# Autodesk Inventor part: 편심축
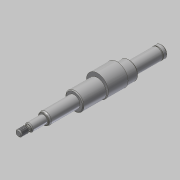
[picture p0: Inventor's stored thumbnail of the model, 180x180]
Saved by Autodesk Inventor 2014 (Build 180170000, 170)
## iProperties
Created: 2015-09
Part Number: 편심축
Material: 강철, 연강
Document SubType Name: Modeling
Designer: mduedu
Density: 1 g/cm^3
Appearance: Steel
Author: mduedu
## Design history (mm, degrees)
sketch "스케치1"
  geometry: L1 (-91, 0)-(91, 0); L2 (-91, 0)-(-91, 7.5); L3 (-91, 7.5)-(-49.85, 7.5); L4 (-49.85, 7.5)-(-49.85, 11.5); L5 (-49.85, 11.5)-(20.15, 11.5); L6 (20.15, 11.5)-(20.15, 7.5); L7 (20.15, 7.5)-(59.15, 7.5); L8 (59.15, 7.5)-(59.15, 5); L9 (59.15, 5)-(78.15, 5); L10 (78.15, 5)-(78.15, 3); L11 (78.15, 3)-(80.15, 3); L12 (81.882, 4)-(91, 4); L13 (91, 4)-(91, 0); L14 (80.15, 3)-(81.882, 4); 2 further points
  constraints: 28 end point, 9 parallel, 2 perpendicular, 1 coincident, 1 collinear, 1 horizontal, 1 midpoint
  dimensions: "d0" = 41.15 distance of L2.end L3.end; "d2" = 70 distance of L4.end L5.end; "d3" = 39 distance of L6.end L7.end; "d4" = 182 distance of L1.start L1.end; "d5" = 19 distance of L8.end L9.end; "d7" = 8 diameter of L12 L1; "d8" = 6 diameter of L11 L1; "d9" = 10 diameter of L9 L1; "d10" = 15 diameter of L7 L1; "d11" = 23 diameter of L5 L1; "d12" = 15 diameter of L3 L1; "d40" = 30 deg angle of L14 L12; "d41" = 2 distance of L10.end L11.end; "d42" = 3.73205 horizontal distance of L12.start L10.end (derived)
revolve "회전1" sketch "스케치1" stored, may be unused: angle "d13" = 90 deg
fillet "모깎기1" dims "d43" = 0.6
sketch "스케치2"
  geometry: L1 (-91, 7.5)-(-49.85, 7.5) reference; L2 (-91, -7.5)-(-91, 7.5) reference; L3 (91, -4)-(91, 4) reference; L4 (-91, 0)-(91, 0); L5 (-86, 7.5)-(-84.85, 7.5); L6 (-84.85, 7.5)-(-84.85, 7.15); L7 (-84.85, 7.15)-(-86, 7.15); L8 (-86, 7.15)-(-86, 7.5); 1 further point
  constraints: 10 end point, 2 midpoint, 2 parallel, 1 horizontal, 1 perpendicular, 1 point on line
  dimensions: "d14" = 5 distance between parallel lines of L8 L2; "d15" = 14.3 diameter of L7 L4; "d16" = 1.15 distance of L6.end L7.end
revolve "회전2" sketch "스케치2" stored, may be unused: angle "d17" = 90 deg
node "작업 평면1"
sketch "스케치3"
  geometry: C1 r 11.5 at (0, 0) reference; C2 r 14 at (0, 2.5); 1 further point
  constraints: 1 centre point, 1 tangent, 1 vertical alignment
  dimensions: "d19" = 28 diameter of C2
extrude "돌출1" join sketch "스케치3" distance "d21" = 25; taper "d22" = 0 deg
node "작업 평면2"
sketch "스케치4"
  geometry: L1 (9.5, 7.5)-(9.5, -7.5) reference; L2 (-9.5, 5)-(-9.5, -5) reference; L3 (9.5, 0)-(-9.5, 0); L4 (-5, -1.5)-(4, -1.5); L5 (4, 1.5)-(-5, 1.5); A1 r 1.5 centre (4, 0) between (4, -1.5) and (4, 1.5); A2 r 1.5 centre (-5, 0) between (-5, 1.5) and (-5, -1.5); 1 further point
  constraints: 6 end point, 4 point on circle, 4 tangent, 2 centre point, 2 midpoint, 2 parallel, 1 point on line
  dimensions: "d23" = 3 distance between parallel lines of L5 L4; "d25" = 12 dimension on A2 A1; "d26" = 3 distance edge to line of A2 L2
extrude "돌출2" cut sketch "스케치4" distance "d27" = 1.8; taper "d28" = 0 deg
chamfer "모따기1" distance "d29" = 1; stored, may be unused: second distance "d30" = 2, angle "d31" = 45 deg
sketch "스케치5"
  geometry: L1 (80.289, 3.08)-(81.882, 4) reference; L2 (81.882, 4)-(91, 4) reference; L3 (91, 4)-(91, -4) reference; L4 (91, -4)-(81.882, -4) reference; L5 (81.882, -4)-(80.289, -3.08) reference; L6 (79.989, -3)-(78.75, -3) reference; L7 (78.15, -3.6)-(78.15, -5) reference; L8 (78.15, -5)-(75.15, -5) reference; L9 (75.15, -5)-(75.15, -3.2) reference; L10 (75.15, -3.2)-(63.15, -3.2) reference; L11 (63.15, -3.2)-(63.15, -5) reference; L12 (63.15, -5)-(59.15, -5) reference; L13 (59.15, -5)-(59.15, -7.5) reference; L14 (59.15, -7.5)-(20.15, -7.5) reference; L15 (20.15, -7.5)-(20.15, -10.5) reference; L16 (20.15, -10.5)-(19.15, -11.5) reference; L17 (19.15, -11.5)-(-9.35, -11.5) reference; L18 (-9.35, -11.5)-(-34.35, -11.5) reference; L19 (-34.35, -11.5)-(-48.85, -11.5) reference; L20 (-48.85, -11.5)-(-49.85, -10.5) reference; L21 (-49.85, -10.5)-(-49.85, -7.5) reference; L22 (-49.85, -7.5)-(-84.85, -7.5) reference; L23 (-84.85, -7.5)-(-84.85, -7.15) reference; L24 (-84.85, -7.15)-(-86, -7.15) reference; L25 (-86, -7.15)-(-86, -7.5) reference; L26 (-86, -7.5)-(-90, -7.5) reference; L27 (-90, -7.5)-(-91, -6.5) reference; L28 (-91, -6.5)-(-91, 6.5) reference; L29 (-91, 6.5)-(-90, 7.5) reference; L30 (-90, 7.5)-(-86, 7.5) reference; L31 (-86, 7.5)-(-86, 7.15) reference; L32 (-86, 7.15)-(-84.85, 7.15) reference; L33 (-84.85, 7.15)-(-84.85, 7.5) reference; L34 (-84.85, 7.5)-(-49.85, 7.5) reference; L35 (-49.85, 7.5)-(-49.85, 10.5) reference; L36 (-49.85, 10.5)-(-48.85, 11.5) reference; L37 (-48.85, 11.5)-(-34.35, 11.5) reference; L38 (-34.35, 11.5)-(-34.35, 16.5) reference; L39 (-34.35, 16.5)-(-9.35, 16.5) reference; L40 (-9.35, 16.5)-(-9.35, 11.5) reference; L41 (-9.35, 11.5)-(19.15, 11.5) reference; L42 (19.15, 11.5)-(20.15, 10.5) reference; L43 (20.15, 10.5)-(20.15, 7.5) reference; L44 (20.15, 7.5)-(59.15, 7.5) reference; L45 (59.15, 7.5)-(59.15, 5) reference; L46 (59.15, 5)-(78.15, 5) reference; L47 (78.15, 5)-(78.15, 3.6) reference; L48 (78.75, 3)-(79.989, 3) reference; L49 (0, 0)-(91, 0); L50 (59.15, -6.55)-(57.505, -7.5); L51 (57.505, -7.5)-(59.15, -7.5); L52 (59.15, -7.5)-(59.15, -6.55); A1 r 0.6 centre (79.989, 3.6) between (79.989, 3) and (80.289, 3.08) reference; A2 r 0.6 centre (79.989, -3.6) between (80.289, -3.08) and (79.989, -3) reference; A3 r 0.6 centre (78.75, -3.6) between (78.75, -3) and (78.15, -3.6) reference; A4 r 0.6 centre (78.75, 3.6) between (78.15, 3.6) and (78.75, 3) reference
  constraints: 8 end point, 2 point on line, 1 midpoint, 1 parallel, 1 perpendicular
  dimensions: "d44" = 30 deg angle of L50 L51; "d45" = 13.1 diameter of L50.start L49
revolve "회전3" sketch "스케치5" stored, may be unused: angle "d46" = 90 deg
fillet "모깎기2" dims "d47" = 4, "d48" = 0.5
feature "스레드1" dims "d32" = 10, "d33" = 0
chamfer "모따기2" distance "d34" = 1; stored, may be unused: second distance "d35" = 2, angle "d36" = 45 deg
chamfer "모따기3" distance "d37" = 1; stored, may be unused: second distance "d38" = 2, angle "d39" = 45 deg
node "솔리드1"
node "절단 모서리 투영1"
other parameters: "d18" = -29.5
